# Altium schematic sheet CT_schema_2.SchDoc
size 276 x 169 mm
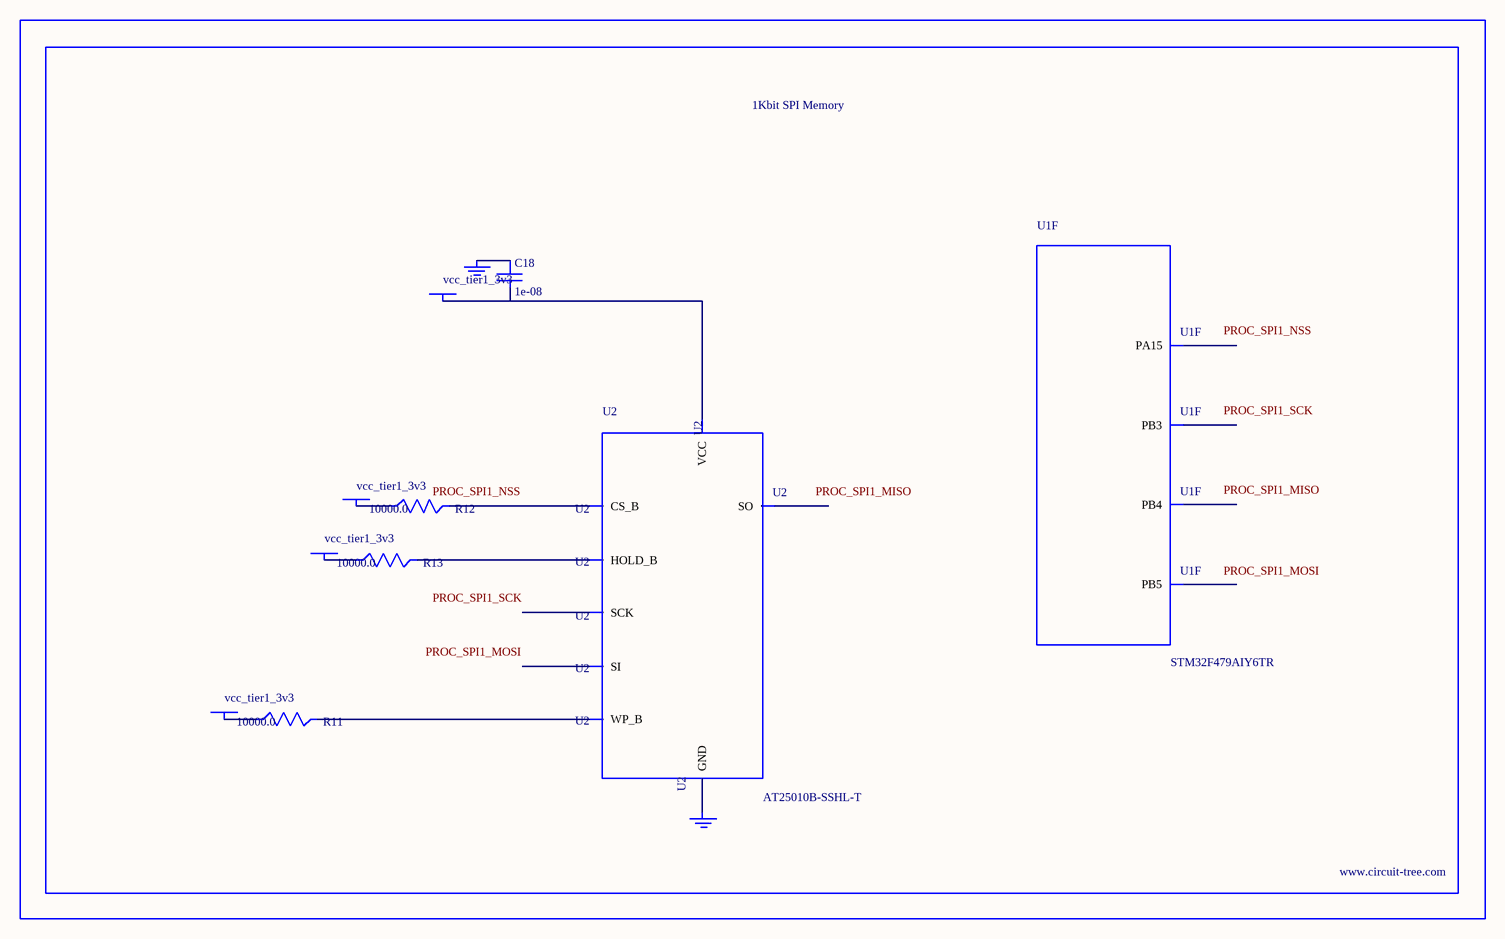
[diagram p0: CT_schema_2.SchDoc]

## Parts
BORDER1  (no value)
C18  1e-08  [C0402]
GND_INSTANCE_1_0  (no value)
GND_INSTANCE_1_1  (no value)
POWER_INSTANCE_1_0  vcc_tier1_3v3
POWER_INSTANCE_1_1  vcc_tier1_3v3
POWER_INSTANCE_1_2  vcc_tier1_3v3
POWER_INSTANCE_1_3  vcc_tier1_3v3
R11  10000.0  [R0603]
R12  10000.0  [R0603]
R13  10000.0  [R0603]
U1  STM32F479AIY6TR  [WLCSP168]  (part F of 13)
U2  AT25010B-SSHL-T  [SOIC-8]

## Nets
NetC18_1: C18.1 GND_INSTANCE_1_0.0(GND)
NetC18_2: C18.2 POWER_INSTANCE_1_3.0(PWR) U2.8(VCC)
NetGND_INSTANCE_1_1_0: GND_INSTANCE_1_1.0(GND) U2.4(GND)
NetPOWER_INSTANCE_1_0_0: POWER_INSTANCE_1_0.0(PWR) R12.1
NetPOWER_INSTANCE_1_1_0: POWER_INSTANCE_1_1.0(PWR) R11.1
NetPOWER_INSTANCE_1_2_0: POWER_INSTANCE_1_2.0(PWR) R13.1
NetR11_2: R11.2 U2.3(WP_B)
NetR12_2: R12.2 U2.1(CS_B)
NetR13_2: R13.2 U2.7(HOLD_B)

Not connected (* = marked no-connect by the designer): U1 A2(PA15) A8(PB3) B8(PB5) C8(PB4); U2 2(SO) 5(SI) 6(SCK)

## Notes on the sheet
- Labels drawn without touching a wire or pin: PROC_SPI1_MISO, PROC_SPI1_MOSI, PROC_SPI1_NSS, PROC_SPI1_SCK

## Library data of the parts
BORDER1 = BORDER_PAGE1
C18 = C0402C103K3RAC
GND_INSTANCE_1_0 GND_INSTANCE_1_1 = GND
POWER_INSTANCE_1_0-POWER_INSTANCE_1_3 = PWR
R11-R13 = RC0603JR-0710KL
